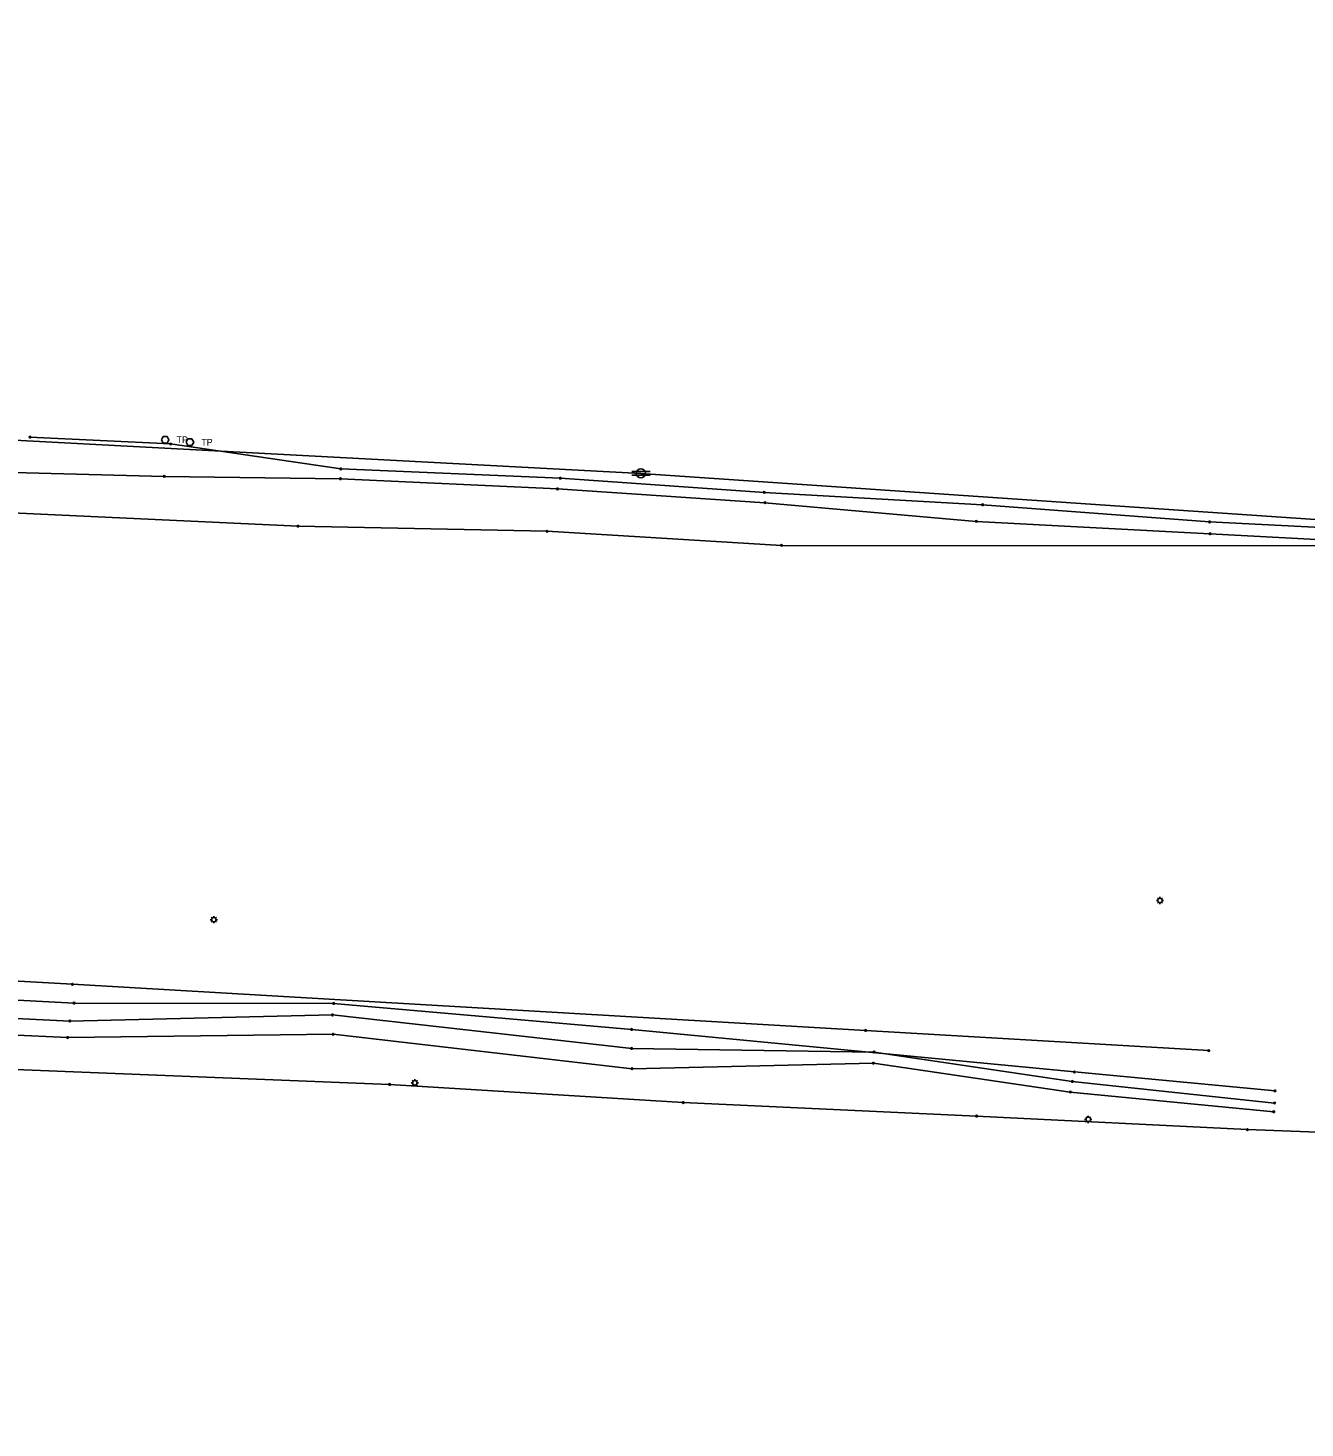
# Model space of a CAD drawing. Extents: x 20500343 to 20505311, y 7953484 to 7954193.
# Drawn here: x 20504690.8 to 20504997.9, y 7953484.1 to 7953820.7 of the extents above; entities that cross this region are included whole.
import ezdxf

# ---------------------------------------------------------------- set-up
doc = ezdxf.new("R2010")
doc.units = 0
for name, color, linetype in [('C-PROP-LINE-LOT', 7, 'Continuous'), ('V-ANNO-NOTE', 7, 'Continuous'), ('V-CTRL-HVPT', 7, 'Continuous'), ('V-MON-FND', 7, 'Continuous')]:
    doc.layers.add(name, color=color, linetype=linetype)

msp = doc.modelspace()

# ---------------------------------------------------------------- linework, layer by layer
at = {"layer": 'C-PROP-LINE-LOT'}
for points in [[(20503437.68, 7953820.69), (20503685.54, 7953801.97), (20503900.73, 7953784.06), (20504174.6, 7953760.81), (20504420.99, 7953738.08), (20504670.9, 7953722.47), (20504838.2, 7953713.61), (20505006.28, 7953702.11), (20505174.11, 7953700.54)], [(20503699.26, 7953775.1), (20503803.54, 7953764.58), (20503866.33, 7953759.03), (20503928.53, 7953761.61), (20504053.64, 7953746.16), (20504141.91, 7953734.18), (20504242.25, 7953732.31), (20504268.23, 7953730.01), (20504338.72, 7953728.07), (20504367.8, 7953726.96), (20504422.51, 7953721.81), (20504479.99, 7953718.52), (20504541.43, 7953712.4), (20504605.71, 7953707.78), (20504671.49, 7953704.84), (20504755.78, 7953700.92), (20504815.67, 7953699.69), (20504872.03, 7953696.31), (20505039.13, 7953696.21), (20505092.16, 7953700.52), (20505136.96, 7953703.53), (20505186.48, 7953709.16)], [(20504210.51, 7953740.4), (20504276.78, 7953736.15), (20504317.11, 7953736.51), (20504358.06, 7953737.31), (20504412.3, 7953733.34), (20504478.84, 7953727.73), (20504548.56, 7953722.54), (20504593.65, 7953719.05), (20504644.38, 7953715.53), (20504690.36, 7953713.78), (20504723.6, 7953712.89), (20504765.96, 7953712.31), (20504818.14, 7953709.88), (20504868.03, 7953706.56), (20504918.85, 7953702.08), (20504975.03, 7953699.08), (20505009.69, 7953697.2), (20505013.14, 7953700.37), (20505013.9, 7953705.42)], [(20504691.32, 7953722.32), (20504725.14, 7953720.68), (20504766.04, 7953714.69), (20504818.85, 7953712.46), (20504867.86, 7953709.05), (20504920.37, 7953706.07), (20504974.93, 7953701.95), (20505009.55, 7953700.17), (20505012.95, 7953705.6)], [(20504024.77, 7953669.37), (20504354.36, 7953613.84), (20504403.94, 7953611.06), (20504480.92, 7953605.95), (20504541.55, 7953600.29), (20504620.66, 7953595.28), (20504701.53, 7953590.77), (20504892.22, 7953579.68), (20504974.75, 7953574.83)], [(20504246.56, 7953616.51), (20504293.41, 7953612.16), (20504342.32, 7953610.98), (20504402.14, 7953607.9), (20504485.85, 7953600.21), (20504541.12, 7953597.7), (20504568.97, 7953596.35), (20504645.79, 7953589.23), (20504701.93, 7953586.24), (20504764.32, 7953586.16), (20504836, 7953579.91), (20504942.46, 7953569.69), (20504990.68, 7953565.15)], [(20504245.01, 7953609.59), (20504293.38, 7953609.52), (20504342.41, 7953608.24), (20504400.78, 7953602.78), (20504485.23, 7953596.26), (20504540.28, 7953594.35), (20504568.66, 7953593.24), (20504644.38, 7953584.7), (20504700.91, 7953581.94), (20504764.05, 7953583.43), (20504836, 7953575.34), (20504894.29, 7953574.48), (20504941.93, 7953567.42), (20504990.58, 7953562.23)], [(20504304.58, 7953566.63), (20504316.99, 7953586.74), (20504318.02, 7953597.08), (20504342.01, 7953606.04), (20504399.08, 7953600.17), (20504485.6, 7953592.38), (20504540.92, 7953587.54), (20504567.5, 7953585.67), (20504644.21, 7953580.53), (20504700.38, 7953577.98), (20504764.23, 7953578.75), (20504836.1, 7953570.47), (20504894.11, 7953571.81), (20504941.45, 7953564.86), (20504990.37, 7953560.12)], [(20504269.22, 7953602.59), (20504316.87, 7953595.9), (20504390.54, 7953591.68), (20504433.07, 7953588.04), (20504524.61, 7953579.67), (20504571.19, 7953575.9), (20504651.75, 7953571.77), (20504777.78, 7953566.7), (20504848.38, 7953562.34), (20504918.92, 7953559.08), (20504984.04, 7953555.83), (20505049.37, 7953553.38), (20505120.36, 7953550.4), (20505152.31, 7953547.69), (20505196.06, 7953544.59), (20505233.38, 7953543.22), (20505244.11, 7953538.95), (20505270.71, 7953516.66), (20505302.37, 7953489.32), (20505310.32, 7953484.09)]]:
    msp.add_lwpolyline(points, dxfattribs=at)
at = {"layer": 'V-ANNO-NOTE'}
for centre in [(20504691.32, 7953722.32), (20504725.14, 7953720.68), (20504766.04, 7953714.69), (20504723.6, 7953712.89), (20504765.96, 7953712.31), (20504818.14, 7953709.88), (20504818.85, 7953712.46), (20504867.86, 7953709.05), (20504868.03, 7953706.56), (20504920.37, 7953706.07), (20504755.78, 7953700.92), (20504815.67, 7953699.69), (20504918.85, 7953702.08), (20504974.93, 7953701.95), (20504872.03, 7953696.31), (20504975.03, 7953699.08), (20504701.53, 7953590.77), (20504701.93, 7953586.24), (20504764.32, 7953586.16), (20504700.91, 7953581.94), (20504764.05, 7953583.43), (20504764.23, 7953578.75), (20504836, 7953579.91), (20504892.22, 7953579.68), (20504700.38, 7953577.98), (20504836, 7953575.34), (20504894.11, 7953571.81), (20504894.29, 7953574.48), (20504974.75, 7953574.83), (20504836.1, 7953570.47), (20504942.46, 7953569.69), (20504777.78, 7953566.7), (20504941.93, 7953567.42), (20504990.68, 7953565.15), (20504848.38, 7953562.34), (20504941.45, 7953564.86), (20504990.58, 7953562.23), (20504918.92, 7953559.08), (20504990.37, 7953560.12), (20504984.04, 7953555.83)]:
    msp.add_circle(centre, 0.2, dxfattribs=at)
at = {"layer": 'V-CTRL-HVPT'}
for p, q in [((20504836, 7953714.05), (20504840.4, 7953714.05)), ((20504836, 7953713.17), (20504840.4, 7953713.17)), ((20504962.14, 7953610.92), (20504962.47, 7953610.92)), ((20504962.4, 7953611.53), (20504962.63, 7953611.3)), ((20504962.4, 7953610.3), (20504962.63, 7953610.53)), ((20504963.01, 7953611.79), (20504963.01, 7953611.46)), ((20504963.01, 7953610.37), (20504963.01, 7953610.05)), ((20504963.39, 7953611.3), (20504963.62, 7953611.53)), ((20504963.39, 7953610.53), (20504963.62, 7953610.3)), ((20504963.55, 7953610.92), (20504963.88, 7953610.92)), ((20504734.66, 7953606.31), (20504734.99, 7953606.31)), ((20504734.92, 7953606.93), (20504735.15, 7953606.7)), ((20504734.92, 7953605.7), (20504735.15, 7953605.93)), ((20504735.53, 7953607.18), (20504735.53, 7953606.85)), ((20504735.53, 7953605.77), (20504735.53, 7953605.44)), ((20504735.91, 7953606.7), (20504736.14, 7953606.93)), ((20504735.91, 7953605.93), (20504736.14, 7953605.7)), ((20504736.07, 7953606.31), (20504736.4, 7953606.31)), ((20504782.98, 7953567.08), (20504783.31, 7953567.08)), ((20504783.24, 7953567.69), (20504783.47, 7953567.46)), ((20504783.24, 7953566.47), (20504783.47, 7953566.7)), ((20504783.85, 7953567.95), (20504783.85, 7953567.62)), ((20504783.85, 7953566.54), (20504783.85, 7953566.21)), ((20504784.23, 7953567.46), (20504784.46, 7953567.69)), ((20504784.23, 7953566.7), (20504784.46, 7953566.47)), ((20504784.39, 7953567.08), (20504784.72, 7953567.08)), ((20504945.16, 7953558.9), (20504945.39, 7953558.67)), ((20504945.77, 7953559.16), (20504945.77, 7953558.83)), ((20504946.15, 7953558.67), (20504946.38, 7953558.9)), ((20504944.9, 7953558.29), (20504945.23, 7953558.29)), ((20504945.16, 7953557.67), (20504945.39, 7953557.9)), ((20504945.77, 7953557.74), (20504945.77, 7953557.42)), ((20504946.15, 7953557.9), (20504946.38, 7953557.67)), ((20504946.31, 7953558.29), (20504946.64, 7953558.29))]:
    msp.add_line(p, q, dxfattribs=at)
for centre, radius in [((20504838.2, 7953713.61), 1.1), ((20504963.01, 7953610.92), 0.543), ((20504735.53, 7953606.31), 0.543), ((20504783.85, 7953567.08), 0.543), ((20504945.77, 7953558.29), 0.543)]:
    msp.add_circle(centre, radius, dxfattribs=at)
at = {"layer": 'V-MON-FND'}
for points in [[(20504722.92, 7953721.7), (20504723.37, 7953722.49), (20504724.29, 7953722.49), (20504724.74, 7953721.7), (20504724.29, 7953720.91), (20504723.37, 7953720.91), (20504722.92, 7953721.7)], [(20504728.86, 7953721.11), (20504729.31, 7953721.9), (20504730.23, 7953721.9), (20504730.68, 7953721.11), (20504730.23, 7953720.31), (20504729.31, 7953720.31), (20504728.86, 7953721.11)]]:
    msp.add_lwpolyline(points, dxfattribs=at)

# ---------------------------------------------------------------- texts
for p in [(20504726.57, 7953720.9), (20504732.51, 7953720.31)]:
    msp.add_text('TP', height=1.599, dxfattribs=at).set_placement(p)

doc.saveas('drawing.dxf')
